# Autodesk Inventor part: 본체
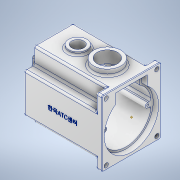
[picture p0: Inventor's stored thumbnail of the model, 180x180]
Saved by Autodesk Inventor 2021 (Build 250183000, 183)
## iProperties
Created: 2022-08
Part Number: 본체
Material: 알루미늄 6061
Document SubType Name: Modeling
Designer: Owner
Mass: 1403.68 g
Surface Area: 1178.8 cm^2
Volume: 519.882 cm^3
Density: 2.7 g/cm^3
Appearance: 알루미늄 - 평지
Author: Owner
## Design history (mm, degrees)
sketch "스케치1"
  geometry: L1 (-55, 49)-(55, 49); L2 (55, 49)-(55, -49); L3 (55, -49)-(-55, -49); L4 (-55, -49)-(-55, 49); L5 (-55, 49)-(55, -49); L6 (55, 49)-(-55, -49); 1 further point
  constraints: 12 end point, 2 midpoint, 2 parallel, 1 horizontal, 1 perpendicular
  dimensions: "d0" = 98 distance between parallel lines of L3 L1; "d1" = 110 distance between parallel lines of L4 L2
extrude "돌출1" new body sketch "스케치1" distance "d2" = 130; taper "d3" = 0 deg
sketch "스케치2"
  geometry: L1 (33, 28)-(65.098, 28); L2 (65.098, 28)-(65.098, 67.939); L3 (65.098, 67.939)-(33, 67.939); L4 (33, 67.939)-(33, 28); L5 (-61.074, 63.678)-(-33, 63.678); L6 (-33, 63.678)-(-33, 28); L7 (-33, 28)-(-61.074, 28); L8 (-61.074, 28)-(-61.074, 63.678); L9 (-57.523, -66.045)-(-33, -66.045); L10 (-33, -66.045)-(-33, -38); L11 (-33, -38)-(-57.523, -38); L12 (-57.523, -38)-(-57.523, -66.045); L13 (61.739, -66.045)-(33, -66.045); L14 (33, -66.045)-(33, -38); L15 (33, -38)-(61.739, -38); L16 (61.739, -38)-(61.739, -66.045); L17 (49, 55)-(-49, 55) reference; L18 (-49, -55)-(49, -55) reference; L19 (49, -55)-(49, 55) reference; 1 further point
  constraints: 32 end point, 8 parallel, 4 horizontal, 4 perpendicular
  dimensions: "d4" = 27 distance between parallel lines of L17 L1; "d5" = 17 distance between parallel lines of L18 L15; "d6" = 17 distance between parallel lines of L18 L11; "d7" = 27 distance between parallel lines of L17 L7; "d8" = 66 distance between parallel lines of L4 L6; "d9" = 66 distance between parallel lines of L14 L10; "d10" = 16 distance between parallel lines of L19 L4; "d11" = 16 distance between parallel lines of L19 L14
extrude "돌출2" cut sketch "스케치2" distance "d12" = 120; taper "d13" = 0 deg
sketch "스케치3"
  geometry: L1 (-27, 33)-(27, 33); L2 (27, 33)-(27, -21); L3 (27, -21)-(-27, -21); L4 (-27, -21)-(-27, 33); L5 (-27, 33)-(27, -21); L6 (27, 33)-(-27, -21); L7 (-33, -55)-(33, -55) reference; 3 further points
  constraints: 12 end point, 2 midpoint, 2 parallel, 1 horizontal, 1 perpendicular, 1 vertical alignment
  dimensions: "d14" = 54 distance between parallel lines of L3 L1; "d15" = 54 distance between parallel lines of L2 L4; "d148" = 61 distance from line of point (0, 6) L7
extrude "돌출3" join sketch "스케치3" distance "d16" = 7; taper "d17" = 0 deg
sketch "스케치4"
  geometry: L1 (0, 98)-(0, 0) reference; C1 r 22.5 at (-40, 49); C2 r 15 at (-89, 49); 2 further points
  constraints: 2 centre point, 2 horizontal alignment, 1 midpoint
  dimensions: "d18" = 45 diameter of C1; "d19" = 30 diameter of C2; "d20" = 40 distance from line of C1.centre L1; "d21" = 49 distance of C2.centre C1.centre
extrude "돌출4" join sketch "스케치4" distance "d22" = 5; taper "d23" = 0 deg
sketch "스케치5"
  geometry: C1 r 22.5 at (0, 0) reference; 1 further point
extrude "돌출5" join sketch "스케치5" distance "d24" = 5; taper "d25" = 0 deg
sketch "스케치6"
  geometry: C1 r 22.5 at (0, 0) reference; 2 further points
  constraints: 1 coincident
hole "구멍1" sketch "스케치6" at (0, 0) diameter "d27" = 33.376; stored, may be unused: countersink angle "d31" = 90 deg, drill point angle "d33" = 0 deg; dims "d28" = 40, "d29" = 4, "d30" = 2, "d32" = 41
sketch "스케치7"
  geometry: C1 r 15 at (0, 0) reference; 2 further points
  constraints: 1 coincident
hole "구멍2" sketch "스케치7" at (0, 0) diameter "d34" = 20; stored, may be unused: countersink angle "d38" = 90 deg, drill point angle "d40" = 0 deg; dims "d35" = 40, "d36" = 4, "d37" = 2, "d39" = 41
sketch "스케치8"
  geometry: L1 (-49, -55)-(49, -55) reference; L2 (-26, 48)-(26, 48); L3 (-26, 48)-(-26, 31.729); L4 (26, 48)-(26, 31.729); A1 r 45 centre (0, -5) between (-26, 31.729) and (26, 31.729); 1 further point
  constraints: 6 end point, 2 point on circle, 1 centre point, 1 horizontal, 1 parallel, 1 perpendicular, 1 vertical, 1 vertical alignment
  dimensions: "d41" = 50 distance from line of L1 A1.centre; "d42" = 90 diameter of A1; "d43" = 53 distance from line of A1.centre L2; "d44" = 52 distance between parallel lines of L4 L3
extrude "돌출6" cut sketch "스케치8" distance "d45" = 9; taper "d46" = 0 deg
sketch "스케치9"
  geometry: L1 (-23, 45)-(23, 45); L2 (-23, 45)-(-23, 30.143); L3 (23, 45)-(23, 30.143); A1 r 45 centre (0, -5) between (-26, 31.729) and (26, 31.729) reference; A2 r 42 centre (0, -5) between (-23, 30.143) and (23, 30.143); 1 further point
  constraints: 6 end point, 2 point on circle, 1 centre point, 1 coincident, 1 horizontal, 1 parallel, 1 perpendicular, 1 vertical
  dimensions: "d47" = 84 diameter of A2; "d48" = 50 distance from line of L1 A1.centre; "d49" = 46 distance between parallel lines of L3 L2
extrude "돌출7" cut sketch "스케치9" distance "d50" = 112; taper "d51" = 0 deg
sketch "스케치10"
  geometry: L1 (-35.778, -1.006)-(-41.81, -1.006); L2 (-35.778, -8.994)-(-41.81, -8.994); L3 (35.778, -1.006)-(41.81, -1.006); L4 (35.778, -8.994)-(41.81, -8.994); A1 r 42 centre (0, -5) between (-23, 30.143) and (23, 30.143) reference; A2 r 36 centre (0, -5) between (-36, -5) and (36, -5); A3 r 4 centre (-36, -5) between (-36.222, -8.994) and (-36.222, -1.006); A4 r 4 centre (36, -5) between (36.222, -1.006) and (36.222, -8.994); A5 r 42 centre (0, -5) between (-23, 30.143) and (23, 30.143) reference; 5 further points
  constraints: 18 point on circle, 8 end point, 6 point on line, 3 centre point, 2 horizontal alignment, 1 coincident, 1 horizontal, 1 parallel
  dimensions: "d52" = 72 diameter of A2; "d53" = 8 diameter of A3; "d54" = 8 diameter of A4
extrude "돌출8" join sketch "스케치10" distance "d55" = 112; taper "d56" = 0 deg
sketch "스케치11"
  geometry: L1 (-49, -55)-(49, -55) reference; A1 r 45 centre (0, -5) between (-26, 31.729) and (26, 31.729) reference; A2 r 21 centre (0, 6) between (8.978, -12.984) and (-8.978, -12.984); A3 r 15 centre (0, -25) between (-8.978, -12.984) and (8.978, -12.984); 1 further point
  constraints: 4 point on circle, 2 centre point, 2 vertical alignment
  dimensions: "d57" = 42 diameter of A2; "d58" = 30 diameter of A3; "d150" = 61 distance from line of A2.centre L1; "d151" = 20 distance of A3.centre A1.centre
extrude "돌출9" join sketch "스케치11" distance "d61" = 7; taper "d62" = 0 deg
sketch "스케치12"
  geometry: A1 r 21 centre (0, 6) between (8.978, -12.984) and (-8.978, -12.984) reference; 2 further points
  constraints: 1 coincident
hole "구멍3" sketch "스케치12" at (0, 6) diameter "d63" = 35; stored, may be unused: countersink angle "d67" = 90 deg, drill point angle "d69" = 0 deg; dims "d64" = 40, "d65" = 4, "d66" = 2, "d68" = 10
sketch "스케치13"
  geometry: A1 r 15 centre (0, -25) between (-8.978, -12.984) and (8.978, -12.984) reference; 2 further points
  constraints: 1 coincident
hole "구멍4" sketch "스케치13" at (0, -25) diameter "d70" = 22; stored, may be unused: countersink angle "d74" = 90 deg, drill point angle "d76" = 0 deg; dims "d71" = 40, "d72" = 4, "d73" = 2, "d75" = 7
sketch "스케치14"
  geometry: C1 r 17.5 at (0, 0) reference; 2 further points
  constraints: 1 coincident
hole "구멍5" sketch "스케치14" at (0, 0) diameter "d77" = 28; stored, may be unused: countersink angle "d81" = 90 deg, drill point angle "d83" = 0 deg; dims "d78" = 40, "d79" = 4, "d80" = 2, "d82" = 10
sketch "스케치15"
  geometry: A1 r 11 centre (0, 0) between (-5.651, 9.438) and (5.651, 9.438) reference; 2 further points
  constraints: 1 coincident
hole "구멍6" sketch "스케치15" at (0, 0) diameter "d84" = 19; stored, may be unused: countersink angle "d88" = 90 deg, drill point angle "d90" = 0 deg; dims "d85" = 40, "d86" = 4, "d87" = 2, "d89" = 3
sketch "스케치17"
  geometry: L1 (-49, 28)-(-49, 55) reference; L2 (49, 55)-(49, 28) reference; L3 (-49, 55)-(-33, 55) reference; L4 (-49, -55)-(-49, -38) reference; L5 (49, -38)-(49, -55) reference; 5 further points
  dimensions: "d98" = 84 distance of point (42, 48) point (-42, 48); "d99" = 7 distance from line of L1 point (-42, 48); "d100" = 7 distance from line of L2 point (42, 48); "d101" = 7 distance from line of L3 point (-42, 48); "d102" = 7 distance from line of L4 point (-42, -48); "d103" = 7 distance from line of L5 point (42, -48); "d104" = 96 distance of point (-42, -48) point (-42, 48); "d105" = 96 distance of point (42, -48) point (42, 48)
hole "구멍8" sketch "스케치17" at (42, 48), (-42, 48), (-42, -48), (42, -48) diameter "d106" = 7; stored, may be unused: countersink angle "d110" = 90 deg, drill point angle "d112" = 0 deg; dims "d107" = 40, "d108" = 4, "d109" = 2, "d111" = 10
sketch "스케치18"
  geometry: A1 r 4 centre (-36, -5) between (-35.778, -8.994) and (-35.778, -1.006) reference; A2 r 4 centre (36, -5) between (35.778, -1.006) and (35.778, -8.994) reference; 3 further points
  constraints: 2 coincident
hole "구멍9" sketch "스케치18" at (-36, -5), (36, -5) diameter "d113" = 3.242; stored, may be unused: countersink angle "d117" = 90 deg, drill point angle "d119" = 118 deg; dims "d114" = 7, "d115" = 4, "d116" = 2, "d118" = 9
fillet "모깎기1" dims "d120" = 3
fillet "모깎기2" dims "d121" = 3
fillet "모깎기3" dims "d122" = 3
fillet "모깎기4" dims "d123" = 3
fillet "모깎기5" dims "d124" = 3
fillet "모깎기7" dims "d126" = 3
fillet "모깎기8" dims "d130" = 0.3
sketch "스케치19"
  geometry: L1 (-30, -55)-(30, -55) reference; C1 r 16 at (0, 6); A1 r 17.5 centre (0, 6) between (3.463, -11.154) and (-3.463, -11.154) reference; 1 further point
  constraints: 1 centre point
  dimensions: "d134" = 32 diameter of C1; "d149" = 61 distance from line of C1.centre L1
extrude "돌출10" cut sketch "스케치19" distance "d135" = 10; taper "d136" = 0 deg
chamfer "모따기2" distance "d137" = 0.8; stored, may be unused: second distance "d138" = 2, angle "d139" = 30 deg
fillet "모깎기9" dims "d140" = 3
sketch "스케치20"
  geometry: L1 (-3, 87)-(-3, 66) reference; L2 (114, 63)-(0, 63) reference; 3 further points
  constraints: 1 other
  dimensions: "d141" = 65 distance from line of point (62, 30) L1; "d142" = 33 distance from line of L2 point (62, 30)
feature "엠보싱1" sketch "스케치20" dims "d0" = 98, "d1" = 110, "d5" = 17, "d6" = 17, "d9" = 66, "d11" = 16, "d143" = 0.5, "d144" = 0
chamfer "모따기3" distance "d145" = 1; stored, may be unused: second distance "d146" = 2, angle "d147" = 30 deg
node "솔리드1"
feature "A9D066F2-1C7D-4E18-AEED-F7BC21143FA4" dims "d34" = 20, "d35" = 40, "d36" = 4, "d37" = 2, "d38" = 90 deg, "d39" = 41, "d40" = 0
